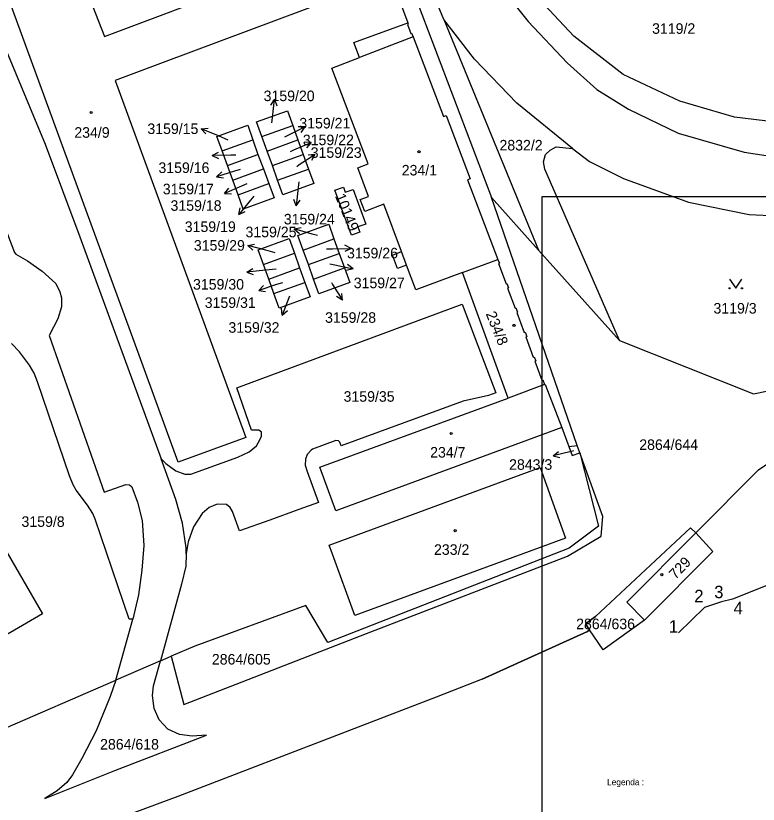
# Model space of a CAD drawing. Extents: x -564952 to -564307, y -1202373 to -1201847.
# Drawn here: x -564730.1 to -564610.5, y -1202086.9 to -1201959.8 of the extents above; entities that cross this region are included whole.
import ezdxf

# ---------------------------------------------------------------- set-up
doc = ezdxf.new("R2010")
doc.units = 0
for name, color, linetype in [('Hranice parcel', 7, 'Continuous'), ('Parcelní čísla', 7, 'Continuous'), ('Pop  PČ popisy', 7, 'Continuous'), ('PS 50-14-01 body', 7, 'Continuous'), ('PS 50-14-01 chránička', 7, 'Continuous'), ('Vnitřní kresba', 7, 'Continuous'), ('Vrstva 31', 7, 'Continuous'), ('Vrstva 63', 7, 'Continuous'), ('Značky budov', 7, 'Continuous'), ('Značky kultur', 7, 'Continuous')]:
    doc.layers.add(name, color=color, linetype=linetype)

msp = doc.modelspace()

# ---------------------------------------------------------------- linework, layer by layer
at = {"layer": 'Hranice parcel'}
for p, q in [((-564668.12, -1201950.64), (-564653.5, -1201989.14)), ((-564661.15, -1201960.44), (-564645.92, -1201997.62)), ((-564690.51, -1201979.3), (-564685.53, -1201977.5)), ((-564685.53, -1201977.5), (-564684.68, -1201979.84)), ((-564696.9, -1201981.63), (-564691.97, -1201979.84)), ((-564691.97, -1201979.84), (-564691.12, -1201982.19)), ((-564689.66, -1201981.66), (-564690.51, -1201979.3)), ((-564689.66, -1201981.66), (-564684.68, -1201979.84)), ((-564684.68, -1201979.84), (-564683.82, -1201982.19)), ((-564696.05, -1201983.98), (-564696.9, -1201981.63)), ((-564696.05, -1201983.98), (-564691.12, -1201982.19)), ((-564691.12, -1201982.19), (-564690.21, -1201984.52)), ((-564688.8, -1201984), (-564689.66, -1201981.66)), ((-564688.8, -1201984), (-564683.82, -1201982.19)), ((-564683.82, -1201982.19), (-564682.97, -1201984.54)), ((-564695.19, -1201986.33), (-564696.05, -1201983.98)), ((-564695.19, -1201986.33), (-564690.21, -1201984.52)), ((-564690.21, -1201984.52), (-564689.36, -1201986.87)), ((-564687.95, -1201986.35), (-564688.8, -1201984)), ((-564687.95, -1201986.35), (-564682.97, -1201984.54)), ((-564694.34, -1201988.68), (-564695.19, -1201986.33)), ((-564694.34, -1201988.68), (-564689.36, -1201986.87)), ((-564653.5, -1201989.14), (-564645.92, -1201997.62)), ((-564639.69, -1202029.09), (-564653.5, -1201989.14)), ((-564683.85, -1201997.6), (-564678.88, -1201995.79)), ((-564678.88, -1201995.79), (-564678.02, -1201998.14)), ((-564683, -1201999.95), (-564683.85, -1201997.6)), ((-564645.92, -1201997.62), (-564632.9, -1202012.18)), ((-564690.24, -1201999.92), (-564685.26, -1201998.11)), ((-564685.26, -1201998.11), (-564684.41, -1202000.46)), ((-564683, -1201999.95), (-564678.02, -1201998.14)), ((-564678.02, -1201998.14), (-564677.17, -1202000.49)), ((-564658.18, -1202001.22), (-564652.47, -1201999.1)), ((-564689.39, -1202002.28), (-564690.24, -1201999.92)), ((-564682.15, -1202002.3), (-564683, -1201999.95)), ((-564689.39, -1202002.28), (-564684.41, -1202000.46)), ((-564684.41, -1202000.46), (-564683.56, -1202002.81)), ((-564682.15, -1202002.3), (-564677.17, -1202000.49)), ((-564650.82, -1202021.45), (-564658.18, -1202001.22)), ((-564688.54, -1202004.62), (-564689.39, -1202002.28)), ((-564688.54, -1202004.62), (-564683.56, -1202002.81)), ((-564644.94, -1202019.28), (-564650.82, -1202021.45)), ((-564642.16, -1202026.18), (-564678.58, -1202039.62)), ((-564642.16, -1202026.18), (-564641.02, -1202029.26)), ((-564641.02, -1202029.26), (-564639.69, -1202029.09)), ((-564639.28, -1202030.26), (-564639.69, -1202029.09)), ((-564610.49, -1202033.02), (-564620.58, -1202043.17)), ((-564714.05, -1202066.95), (-564711.28, -1202057.08)), ((-564701.32, -1202061.43), (-564705.09, -1202063.07)), ((-564706.83, -1202063.82), (-564714.05, -1202066.95)), ((-564706.83, -1202063.82), (-564705.09, -1202063.07)), ((-564748.68, -1202081.97), (-564714.05, -1202066.95))]:
    msp.add_line(p, q, dxfattribs=at)
for points in [[(-564686.16, -1201871.23), (-564677.08, -1201895.29), (-564660.17, -1201939.88), (-564659.23, -1201942.17), (-564652.34, -1201954.8), (-564647.57, -1201960.74), (-564641.3, -1201967.43), (-564636.51, -1201971.74), (-564631.4, -1201974.9), (-564623.41, -1201978.76)], [(-564661.15, -1201960.44), (-564670.99, -1201936.66), (-564694.16, -1201875.63)], [(-564711.3, -1202011.73), (-564714.18, -1202003.86), (-564737.5, -1201940.24), (-564726.36, -1201936.19)], [(-564726.36, -1201936.19), (-564715.86, -1201963.16), (-564672.37, -1201946.79)], [(-564743.87, -1201974.68), (-564742.68, -1201973.7), (-564742.16, -1201972.86), (-564756.86, -1201945.42), (-564755.16, -1201944.44), (-564755.45, -1201943.97), (-564751.11, -1201941.46), (-564745.96, -1201938.44), (-564740.22, -1201948.79), (-564732.79, -1201962.98), (-564725.4, -1201980.52), (-564719.8, -1201995.48), (-564706.71, -1202031.28)], [(-564596.05, -1201977.38), (-564604.58, -1201977.37), (-564614.37, -1201976.21), (-564623.15, -1201973.61), (-564632.26, -1201969.32), (-564640.22, -1201963.11), (-564646.58, -1201956.32), (-564653.95, -1201945.36)], [(-564669.89, -1201953.65), (-564706.41, -1201967.36), (-564714.12, -1201970.26), (-564699.64, -1202009.87)], [(-564669.89, -1201953.65), (-564669.13, -1201955.68), (-564668.99, -1201955.63), (-564666.96, -1201960.96)], [(-564674.77, -1201966.57), (-564675.67, -1201964.13), (-564666.96, -1201960.96)], [(-564666.96, -1201960.96), (-564666.9, -1201961.19), (-564667.04, -1201961.24), (-564666.5, -1201962.69), (-564666.36, -1201962.64), (-564666.14, -1201963.23), (-564661.24, -1201976.08), (-564660.82, -1201975.92), (-564656.92, -1201986.14), (-564657.34, -1201986.3), (-564652.47, -1201999.1)], [(-564640.45, -1201981.26), (-564649.4, -1201973.92), (-564656.22, -1201966.86), (-564661.15, -1201960.44)], [(-564674.66, -1201989.46), (-564673.31, -1201988.97), (-564675.04, -1201984.36), (-564673.36, -1201983.73), (-564679.22, -1201968.26), (-564674.77, -1201966.57)], [(-564690.51, -1201979.3), (-564691.37, -1201976.95), (-564686.39, -1201975.14), (-564685.53, -1201977.5)], [(-564696.9, -1201981.63), (-564697.76, -1201979.28), (-564692.78, -1201977.47), (-564691.97, -1201979.84)], [(-564623.41, -1201978.76), (-564612.8, -1201981.8), (-564605.69, -1201982.88)], [(-564738.81, -1201981.26), (-564737.28, -1201981.76), (-564736.22, -1201982.93), (-564735.6, -1201984.35), (-564730.37, -1201997.98), (-564730.11, -1201998.29), (-564728.24, -1201999.36), (-564725.88, -1202000.98), (-564723.7, -1202002.98), (-564723.06, -1202004.34), (-564722.79, -1202005.32), (-564722.8, -1202006.77), (-564723.36, -1202008.7), (-564724.79, -1202011.36), (-564715.88, -1202036.65), (-564712.4, -1202035.41), (-564711.8, -1202035.46), (-564711.42, -1202035.78), (-564710.52, -1202038.26), (-564709.8, -1202041.19), (-564709.53, -1202045.2), (-564709.81, -1202049.19), (-564710.38, -1202053.2), (-564711.28, -1202057.08)], [(-564632.9, -1202012.18), (-564644.89, -1201984.55), (-564645.1, -1201983.38), (-564644.79, -1201982.21), (-564644.06, -1201981.48), (-564643.08, -1201980.96), (-564640.45, -1201981.26)], [(-564640.45, -1201981.26), (-564637.68, -1201983.33), (-564632.21, -1201986.09), (-564621.75, -1201989.88), (-564611.99, -1201991.88), (-564598.44, -1201992.53), (-564592.52, -1201992.17), (-564572.99, -1201990.58)], [(-564682.97, -1201984.54), (-564682.11, -1201986.9), (-564687.1, -1201988.71), (-564687.95, -1201986.35)], [(-564689.36, -1201986.87), (-564688.5, -1201989.21), (-564693.49, -1201991.02), (-564694.34, -1201988.68)], [(-564676.05, -1201995.18), (-564678.75, -1201987.93), (-564677.35, -1201987.47), (-564677.08, -1201988.29), (-564675.81, -1201987.83), (-564673.77, -1201993.41), (-564675.04, -1201993.86), (-564674.72, -1201994.71), (-564676.05, -1201995.18)], [(-564670.86, -1201990.22), (-564673.93, -1201991.38), (-564674.66, -1201989.46)], [(-564658.18, -1202001.22), (-564665.67, -1202004), (-564667.17, -1202000.05), (-564668.64, -1202000.6), (-564669.47, -1201998.42), (-564668, -1201997.86), (-564670.86, -1201990.22)], [(-564683.85, -1201997.6), (-564684.71, -1201995.25), (-564679.73, -1201993.44), (-564678.88, -1201995.79)], [(-564690.24, -1201999.92), (-564691.1, -1201997.57), (-564686.12, -1201995.76), (-564685.26, -1201998.11)], [(-564652.47, -1201999.1), (-564652.23, -1201999.73), (-564652.37, -1201999.78), (-564651.16, -1202003.03), (-564651.02, -1202002.98), (-564650.76, -1202003.69), (-564650.9, -1202003.74), (-564649.69, -1202006.97), (-564649.55, -1202006.92), (-564649.3, -1202007.6), (-564649.44, -1202007.66), (-564648.23, -1202010.89), (-564648.09, -1202010.84), (-564647.83, -1202011.54), (-564647.97, -1202011.59), (-564646.76, -1202014.84), (-564646.62, -1202014.79), (-564646.36, -1202015.47), (-564646.5, -1202015.52), (-564645.36, -1202018.59), (-564645.22, -1202018.54), (-564644.94, -1202019.28)], [(-564655, -1202066.79), (-564638.03, -1202059.06), (-564637.69, -1202058.81), (-564638.33, -1202057.87), (-564636.74, -1202056.66), (-564621.41, -1202042.36), (-564620.58, -1202043.17), (-564610.49, -1202033.02), (-564584.31, -1202015.23), (-564579.06, -1202011.62), (-564576.04, -1202009.54), (-564575.81, -1202009.88), (-564559.51, -1202001.15), (-564554.04, -1201999.85), (-564546.86, -1201999.32), (-564540.29, -1202000.14), (-564533.65, -1202003.36), (-564528.41, -1202007.65), (-564524, -1202013.27)], [(-564677.17, -1202000.49), (-564676.31, -1202002.84), (-564681.29, -1202004.65), (-564682.15, -1202002.3)], [(-564683.56, -1202002.81), (-564682.71, -1202005.16), (-564687.69, -1202006.97), (-564688.54, -1202004.62)], [(-564706.71, -1202031.28), (-564705.96, -1202031.99), (-564704.35, -1202033.17), (-564702.93, -1202033.73), (-564701.92, -1202033.71), (-564694.37, -1202031), (-564692.56, -1202030.14), (-564691.38, -1202029.17), (-564690.8, -1202028.17), (-564690.57, -1202027.61), (-564690.58, -1202026.98), (-564690.99, -1202026.62), (-564692.16, -1202026.62), (-564694.55, -1202019.79), (-564658.22, -1202006.34), (-564655.12, -1202014.55), (-564652.79, -1202020.62), (-564653.96, -1202021.05), (-564658.06, -1202021.97), (-564677.71, -1202029.18), (-564677.93, -1202028.58), (-564678.14, -1202028.33), (-564678.57, -1202028.28), (-564682.34, -1202029.71), (-564682.55, -1202029.87), (-564683.17, -1202030.58), (-564683.49, -1202031.3), (-564683.53, -1202032.28), (-564683.19, -1202033.3), (-564681.37, -1202038.27), (-564684.52, -1202039.4), (-564689.21, -1202041.12), (-564694.08, -1202042.88), (-564695.23, -1202039.76), (-564695.59, -1202039.09), (-564696.21, -1202038.63), (-564697.68, -1202038.54), (-564698.99, -1202039.09), (-564700.12, -1202040.08), (-564701.49, -1202042.19), (-564702.38, -1202044.62), (-564702.69, -1202046.59)], [(-564699.64, -1202009.87), (-564693.09, -1202027.81), (-564704, -1202031.8), (-564711.3, -1202011.73)], [(-564711.28, -1202057.08), (-564711.89, -1202057.07), (-564717.33, -1202041), (-564717.74, -1202040.08), (-564718.61, -1202038.7), (-564720.39, -1202036.28), (-564720.92, -1202035.43), (-564721.5, -1202034.01), (-564726.63, -1202018.86), (-564727.16, -1202017.44), (-564727.95, -1202016.15), (-564729.54, -1202014), (-564730.82, -1202012.69)], [(-564632.9, -1202012.18), (-564611.28, -1202020.76), (-564606.29, -1202019.78)], [(-564644.94, -1202019.28), (-564644.87, -1202019.26), (-564642.16, -1202026.18)], [(-564678.58, -1202039.62), (-564681.14, -1202032.61), (-564650.82, -1202021.45)], [(-564641.02, -1202029.26), (-564640.48, -1202030.71), (-564639.28, -1202030.26)], [(-564705.09, -1202063.07), (-564703.05, -1202070.87), (-564673.66, -1202059.38), (-564641.23, -1202046.96), (-564635.84, -1202043.71), (-564635.54, -1202040.56), (-564639.28, -1202030.26)], [(-564639.28, -1202030.26), (-564636.25, -1202042.12), (-564640.99, -1202045.63), (-564679.85, -1202060.87), (-564683.39, -1202054.87), (-564701.32, -1202061.43)], [(-564702.69, -1202046.59), (-564702.67, -1202045.58), (-564703.28, -1202041.64), (-564704.33, -1202037.8), (-564706.71, -1202031.28)], [(-564760.54, -1202044.37), (-564739.77, -1202032.27), (-564725.85, -1202056.25), (-564767.37, -1202080.44)], [(-564641.55, -1202044.04), (-564675.51, -1202056.52), (-564679.11, -1202046.62), (-564679.66, -1202045.18), (-564645.68, -1202032.66), (-564641.55, -1202044.04)], [(-564620.58, -1202043.17), (-564621.41, -1202042.36), (-564636.74, -1202056.66), (-564638.33, -1202057.87), (-564637.69, -1202058.81)], [(-564620.58, -1202043.17), (-564631.67, -1202054.35), (-564628.87, -1202057.25)], [(-564620.58, -1202043.17), (-564617.83, -1202046.17), (-564628.87, -1202057.25)], [(-564702.69, -1202046.59), (-564702.72, -1202048.57), (-564703.43, -1202051.47), (-564706.83, -1202063.82)], [(-564628.87, -1202057.25), (-564635.48, -1202062.04), (-564637.69, -1202058.81)], [(-564637.69, -1202058.81), (-564638.03, -1202059.06), (-564655, -1202066.79), (-564662.43, -1202069.69), (-564704.06, -1202085.69), (-564722.99, -1202092.74), (-564729.95, -1202095.67), (-564736.84, -1202098.72), (-564741.32, -1202100.95), (-564768.52, -1202116.71), (-564777.25, -1202121.88), (-564783.74, -1202125.64), (-564785.97, -1202126.79), (-564816.39, -1202144.49)], [(-564701.75, -1202075.95), (-564703.77, -1202075.67), (-564705.62, -1202074.81), (-564707.02, -1202073.32), (-564707.86, -1202071.49), (-564708.14, -1202069.39), (-564707.94, -1202067.86), (-564706.83, -1202063.82)], [(-564714.05, -1202066.95), (-564714.91, -1202069.57), (-564717.19, -1202075.12), (-564719.5, -1202079.57), (-564721, -1202082.19), (-564721.93, -1202083.42), (-564723.48, -1202084.75)], [(-564723.48, -1202084.75), (-564725.45, -1202085.98), (-564714.18, -1202081.49), (-564699.41, -1202075.82), (-564701.75, -1202075.95)]]:
    msp.add_lwpolyline(points, dxfattribs=at)
at = {"layer": 'Pop  PČ popisy'}
for p, q in [((-564688.48, -1201973.3), (-564689.08, -1201974.25)), ((-564688.79, -1201976.29), (-564688.48, -1201973.3)), ((-564688.48, -1201973.3), (-564688.08, -1201974.35)), ((-564688.87, -1201977.11), (-564688.79, -1201976.29)), ((-564700.25, -1201978.04), (-564699.14, -1201977.97)), ((-564697.49, -1201979.21), (-564700.25, -1201978.04)), ((-564700.25, -1201978.04), (-564699.53, -1201978.89)), ((-564686.25, -1201979.08), (-564683.55, -1201977.76)), ((-564683.55, -1201977.76), (-564684.67, -1201977.75)), ((-564683.55, -1201977.76), (-564684.23, -1201978.65)), ((-564695.92, -1201979.87), (-564697.49, -1201979.21)), ((-564686.79, -1201979.35), (-564686.25, -1201979.08)), ((-564685.32, -1201981.45), (-564682.56, -1201980.28)), ((-564682.56, -1201980.28), (-564683.68, -1201980.21)), ((-564682.56, -1201980.28), (-564683.28, -1201981.13)), ((-564698.48, -1201982.36), (-564697.49, -1201981.84)), ((-564695.48, -1201982.31), (-564698.48, -1201982.36)), ((-564698.48, -1201982.36), (-564697.47, -1201982.85)), ((-564694.69, -1201982.3), (-564695.48, -1201982.31)), ((-564685.9, -1201981.7), (-564685.32, -1201981.45)), ((-564684.46, -1201983.83), (-564681.94, -1201982.2)), ((-564681.94, -1201982.2), (-564683.06, -1201982.32)), ((-564681.94, -1201982.2), (-564682.51, -1201983.16)), ((-564684.88, -1201984.11), (-564684.46, -1201983.83)), ((-564694.91, -1201984.9), (-564697.78, -1201985.78)), ((-564697.78, -1201985.78), (-564696.97, -1201985.01)), ((-564694.01, -1201984.62), (-564694.91, -1201984.9)), ((-564697.78, -1201985.78), (-564696.68, -1201985.96)), ((-564693.76, -1201987.3), (-564696.52, -1201988.47)), ((-564696.52, -1201988.47), (-564695.8, -1201987.62)), ((-564692.91, -1201986.95), (-564693.76, -1201987.3)), ((-564684.64, -1201987.51), (-564684.95, -1201990.5)), ((-564684.55, -1201986.63), (-564684.64, -1201987.51)), ((-564696.52, -1201988.47), (-564695.41, -1201988.54)), ((-564691.81, -1201988.91), (-564692.33, -1201989.54)), ((-564692.33, -1201989.54), (-564694.22, -1201991.87)), ((-564684.95, -1201990.5), (-564685.35, -1201989.45)), ((-564684.95, -1201990.5), (-564684.35, -1201989.55)), ((-564694.22, -1201991.87), (-564693.98, -1201990.78)), ((-564694.22, -1201991.87), (-564693.2, -1201991.41)), ((-564685.28, -1201994.19), (-564684.17, -1201993.99)), ((-564682.39, -1201995.02), (-564685.28, -1201994.19)), ((-564685.28, -1201994.19), (-564684.45, -1201994.95)), ((-564681.53, -1201995.26), (-564682.39, -1201995.02)), ((-564692.77, -1201996.85), (-564691.67, -1201996.63)), ((-564689.87, -1201997.63), (-564692.77, -1201996.85)), ((-564692.77, -1201996.85), (-564691.93, -1201997.6)), ((-564688.34, -1201998.04), (-564689.87, -1201997.63)), ((-564680.09, -1201997.4), (-564679.13, -1201997.38)), ((-564679.13, -1201997.38), (-564676.13, -1201997.33)), ((-564676.13, -1201997.33), (-564677.14, -1201996.84)), ((-564676.13, -1201997.33), (-564677.12, -1201997.85)), ((-564679.52, -1201999.82), (-564678.74, -1201999.99)), ((-564678.74, -1201999.99), (-564675.81, -1202000.61)), ((-564675.81, -1202000.61), (-564676.68, -1201999.92)), ((-564692.92, -1202001.16), (-564691.97, -1202000.56)), ((-564689.93, -1202000.85), (-564692.92, -1202001.16)), ((-564692.92, -1202001.16), (-564691.87, -1202001.56)), ((-564688.19, -1202000.67), (-564689.93, -1202000.85)), ((-564675.81, -1202000.61), (-564676.89, -1202000.9)), ((-564687.16, -1202002.86), (-564688.16, -1202003.18)), ((-564679.3, -1202002.82), (-564679.1, -1202003.15)), ((-564688.16, -1202003.18), (-564691.01, -1202004.11)), ((-564691.01, -1202004.11), (-564690.22, -1202003.32)), ((-564691.01, -1202004.11), (-564689.91, -1202004.27)), ((-564679.1, -1202003.15), (-564677.51, -1202005.7)), ((-564686.14, -1202005.29), (-564687.21, -1202008.09)), ((-564686.05, -1202005.04), (-564686.14, -1202005.29)), ((-564677.51, -1202005.7), (-564678.46, -1202005.11)), ((-564677.51, -1202005.7), (-564677.62, -1202004.58)), ((-564687.21, -1202008.09), (-564687.32, -1202006.98)), ((-564687.21, -1202008.09), (-564686.39, -1202007.34)), ((-564640.64, -1202030.05), (-564643.55, -1202030.78)), ((-564643.55, -1202030.78), (-564642.7, -1202030.05)), ((-564643.55, -1202030.78), (-564642.46, -1202031.02)), ((-564640.26, -1202029.95), (-564640.64, -1202030.05))]:
    msp.add_line(p, q, dxfattribs=at)
at = {"layer": 'PS 50-14-01 chránička'}
for p, q in [((-564607.33, -1202050.94), (-564614.64, -1202053.89)), ((-564616.45, -1202054.32), (-564619.17, -1202055.21)), ((-564614.64, -1202053.89), (-564616.45, -1202054.32)), ((-564619.17, -1202055.21), (-564623.38, -1202059.32))]:
    msp.add_line(p, q, dxfattribs=at)
at = {"layer": 'Vnitřní kresba'}
for p, q in [((-564666.14, -1201963.23), (-564674.77, -1201966.57)), ((-564667.17, -1202000.05), (-564668, -1201997.86))]:
    msp.add_line(p, q, dxfattribs=at)
at = {"layer": 'Vrstva 31'}
for p, q in [((-564616.45, -1202054.32), (-564616.45, -1202054.32)), ((-564614.64, -1202053.89), (-564614.64, -1202053.89)), ((-564619.17, -1202055.21), (-564619.17, -1202055.21)), ((-564623.38, -1202059.32), (-564623.38, -1202059.32))]:
    msp.add_line(p, q, dxfattribs=at)
at = {"layer": 'Vrstva 63'}
msp.add_lwpolyline([(-564540.34, -1202137.49), (-564645.34, -1202137.49), (-564645.34, -1201988.99), (-564540.34, -1201988.99)], close=True, dxfattribs=at)
at = {"layer": 'Značky budov'}
for centre in [(-564718, -1201975.43), (-564665.18, -1201981.76), (-564649.88, -1202009.75), (-564659.99, -1202027.17), (-564659.34, -1202042.84), (-564626.06, -1202049.91)]:
    msp.add_circle(centre, 0.175, dxfattribs=at)
at = {"layer": 'Značky kultur'}
msp.add_lwpolyline([(-564615.15, -1202002.27), (-564614.15, -1202003.77), (-564613.15, -1202002.27)], dxfattribs=at)
for centre in [(-564615.15, -1202003.77), (-564613.15, -1202003.77)]:
    msp.add_circle(centre, 0.1, dxfattribs=at)

# ---------------------------------------------------------------- texts
at = {"layer": 'Parcelní čísla'}
for s, p in [('3119/2', (-564627.62, -1201962.75)), ('3159/20', (-564690.21, -1201973.6)), ('3159/21', (-564684.46, -1201978)), ('3159/15', (-564708.94, -1201978.9)), ('234/9', (-564720.71, -1201979.5)), ('3159/22', (-564683.89, -1201980.7)), ('2832/2', (-564652.21, -1201981.55)), ('3159/23', (-564682.63, -1201982.74)), ('3159/16', (-564707.16, -1201985.18)), ('234/1', (-564667.96, -1201985.58)), ('3159/17', (-564706.46, -1201988.62)), ('3159/18', (-564705.21, -1201991.28)), ('3159/24', (-564686.96, -1201993.47)), ('3159/19', (-564702.92, -1201994.69)), ('3159/25', (-564693.13, -1201995.54)), ('3159/29', (-564701.45, -1201997.7)), ('3159/26', (-564676.78, -1201998.94)), ('3159/30', (-564701.59, -1202003.98)), ('3159/27', (-564675.69, -1202003.75)), ('3159/31', (-564699.7, -1202006.93)), ('3119/3', (-564617.73, -1202007.84)), ('3159/28', (-564680.31, -1202009.33)), ('3159/32', (-564695.88, -1202010.93)), ('3159/35', (-564677.33, -1202022.05)), ('2864/644', (-564629.69, -1202029.82)), ('234/7', (-564663.38, -1202031.05)), ('2843/3', (-564650.66, -1202033.02)), ('3159/8', (-564729.22, -1202042.22)), ('233/2', (-564662.76, -1202046.73)), ('2864/636', (-564639.86, -1202058.71)), ('2864/605', (-564698.55, -1202064.41)), ('2864/618', (-564716.56, -1202078.11))]:
    msp.add_text(s, height=1.7, dxfattribs=at).set_placement(p)
for s, rotation, p in [('10149', 292, (-564678.74, -1201988.88)), ('234/8', 292, (-564654.45, -1202007.88)), ('729', 46, (-564623.86, -1202050.78))]:
    msp.add_text(s, height=1.7, rotation=rotation, dxfattribs=at).set_placement(p)
at = {"layer": 'PS 50-14-01 body'}
for s, p in [('2', (-564620.82, -1202054.36)), ('3', (-564617.61, -1202053.71)), ('4', (-564614.5, -1202056.3)), ('1', (-564624.92, -1202059.26))]:
    msp.add_text(s, height=2, dxfattribs=at).set_placement(p)
at = {"layer": 'Vrstva 63'}
msp.add_text('Legenda :', height=1, rotation=359.9999, dxfattribs=at).set_placement((-564634.87, -1202083.86))

doc.saveas('drawing.dxf')
